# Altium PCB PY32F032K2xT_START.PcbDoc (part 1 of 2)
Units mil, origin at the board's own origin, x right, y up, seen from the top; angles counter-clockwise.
Board outline 1771.65 x 3929.06 mil, 2 copper layers (Top Layer, Bottom Layer), stack 21 mil thick; 141 components, 132 nets, 501 pads, 346 vias.
Unrouted connection lines stored in the file: 5.
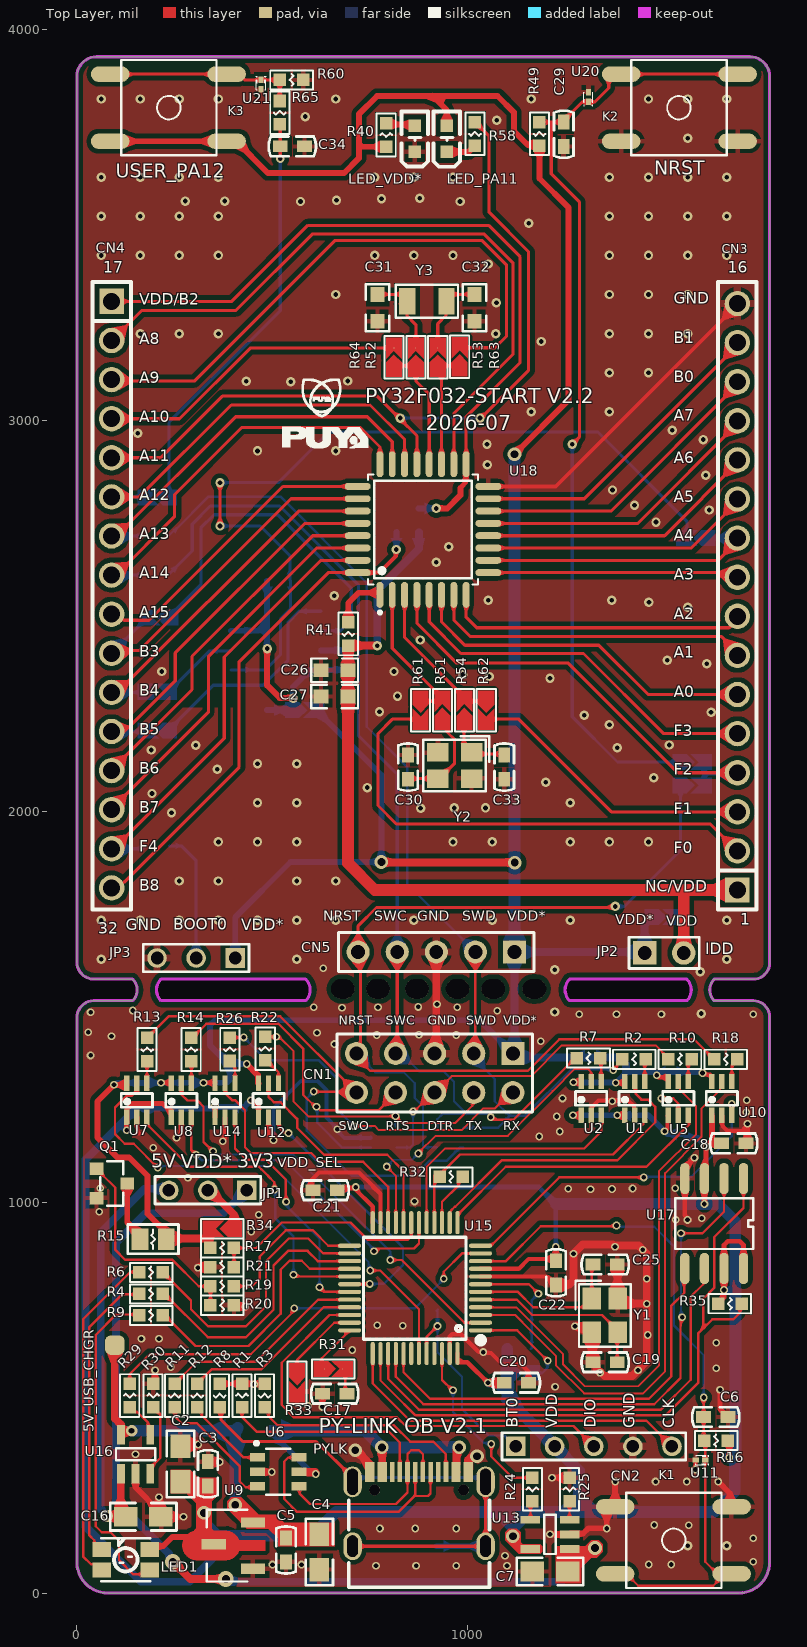
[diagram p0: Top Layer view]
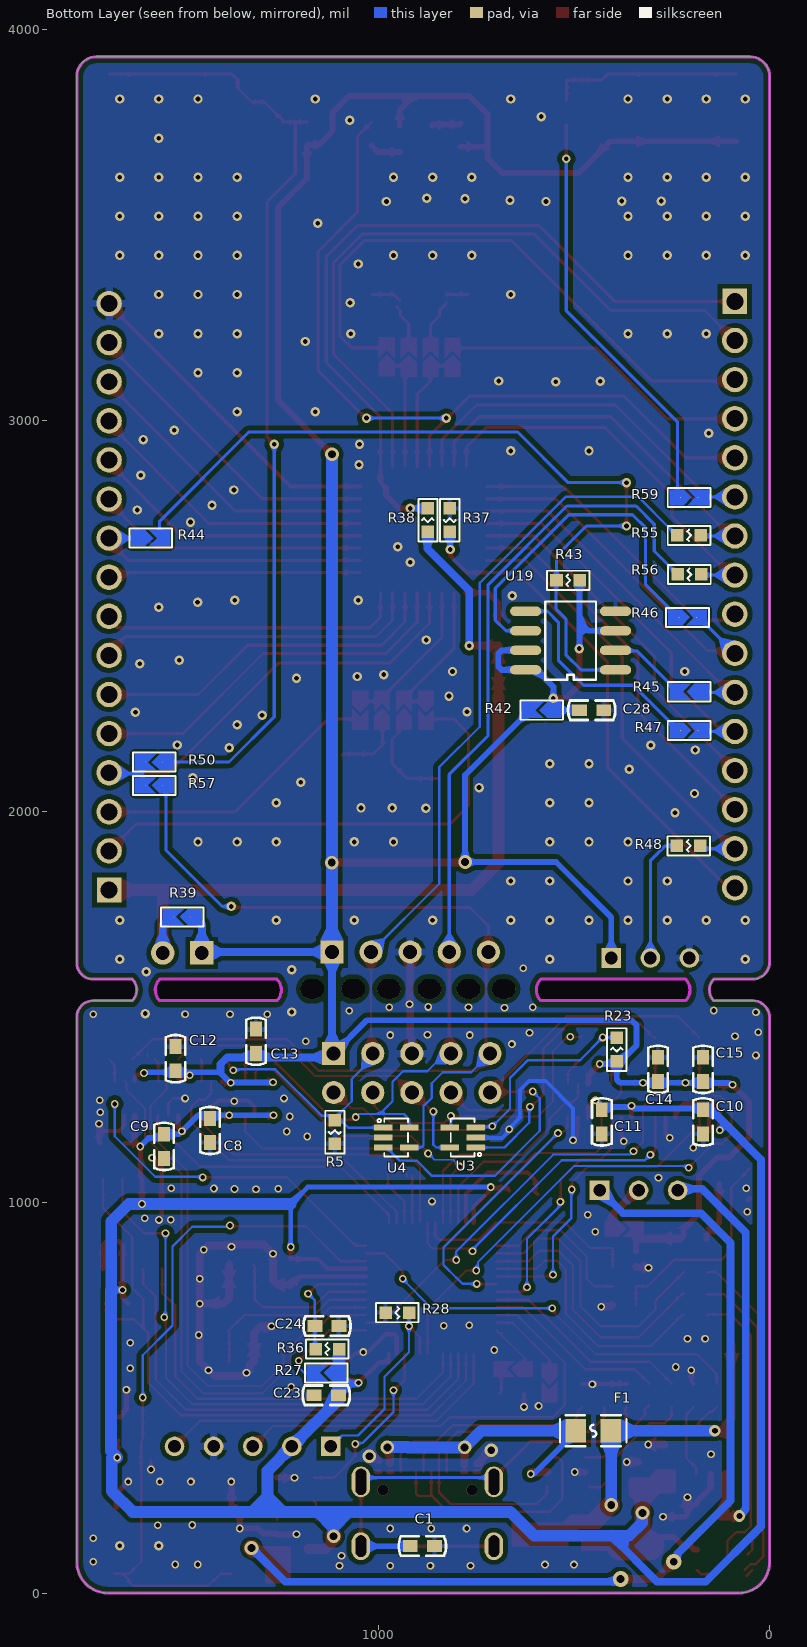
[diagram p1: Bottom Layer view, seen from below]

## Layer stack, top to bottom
Top Solder: solder mask 0.4, Solder Resist, Dk 3.5
Top Layer: signal copper 1.4
Dielectric 2: prepreg 2.8, Composite dielectric, Dk 4.1
Dielectric 1: prepreg 12.6, Composite dielectric, Dk 4.1
Dielectric 3: prepreg 2.8, Composite dielectric, Dk 4.1
Bottom Layer: signal copper 1.4
Bottom Solder: solder mask 0.4, Solder Resist, Dk 3.5

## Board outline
0,78.74 0,1470 cw(c43.75,1471.25) 42.5,1515 142.5,1515 ccw(c115,1542.5) 142.5,1570 42.5,1570 cw(c43.75,1613.75) 0,1615 0,3879.06 cw(c50,3879.06) 50,3929.06 1721.65,3929.06 cw(c1721.65,3879.06) 1771.65,3879.06 1771.65,1611.65 cw(c1730,1611.65) 1730,1570 1630,1570 ccw(c1657.5,1542.5) 1630,1515 1730,1515 cw(c1730,1473.35) 1771.65,1473.35 1771.65,78.74 cw(c1692.91,78.74) 1692.91,0 78.74,0 cw(c78.74,78.74)
cut-out: 1260,1515 cw(c1287.5,1542.5) 1260,1570 1560,1570 cw(c1532.5,1542.5) 1560,1515
cut-out: 215,1515 cw(c242.5,1542.5) 215,1570 585,1570 cw(c557.5,1542.5) 585,1515
cut-out: 215,1515 cw(c242.5,1542.5) 215,1570 585,1570 cw(c557.5,1542.5) 585,1515 565,1515
cut-out: 1260,1515 cw(c1287.5,1542.5) 1260,1570 1560,1570 cw(c1532.5,1542.5) 1560,1515

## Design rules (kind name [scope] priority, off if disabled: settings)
Clearance polygon [InPolygon] p1: gap=12 ignorepadtopadclearanceinfootprint=TRUE
Clearance [All] p2: gap=7 ignorepadtopadclearanceinfootprint=TRUE
HoleToHoleClearance [All] p1: gap=1 allowstackedmicrovias=TRUE
MinimumSolderMaskSliver [All] p1: minsoldermaskwidth=0
PlaneClearance [All] p1: clearance=8
PlaneConnect [All] p1: planeconnectstyle=Direct reliefexpansion=20 reliefentries=4 reliefconductorwidth=10 reliefairgap=10
PolygonConnect [All] p1: thpad.connectstyle=Relief thpad.reliefconductorwidth=20 thpad.reliefentries=4 thpad.polygonreliefangle="90 Angle" thpad.airgapwidth=10 smdpad.connectstyle=Relief smdpad.reliefconductorwidth=12 smdpad.reliefentries=4 smdpad.polygonreliefangle="90 Angle" smdpad.airgapwidth=10 via.connectstyle=Direct via.reliefconductorwidth=10 via.reliefentries=4 via.polygonreliefangle="90 Angle" via.airgapwidth=10
RoutingVias [All] p1: holewidth=28 width=50 viastyle="Through Hole" minholewidth=28 minwidth=50 maxholewidth=28 maxwidth=50
SilkToSilkClearance [All] p1: silktosilkclearance=0
SilkToSolderMaskClearance [IsPad] p1: minsilkscreentomaskgap=0 clearancetoexposedcopper=TRUE
SolderMaskExpansion [All] p1: expansion=4 istentingtop=FALSE
UnRoutedNet [All] p1: checkbadconnections=TRUE
Width [All] p1: maxlimit=100 minlimit=5 preferedwidth=8
23 further rules are at their usual default settings.

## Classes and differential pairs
component class PY32F032K2xT_START: 3 C26 C27 C28 C29 C30 C31 C32 C33 C34 CN3 CN4 CN5 JP2 JP3 K2 K3 LED_PA11 LED_VDD* R37 R38 R39 R40 R41 R42 R43 R44 R45 R46 R47 R48 R49 R50 R51 R52 R53 R54 R55 R56 R57 R58 R59 R60 R61 R62 R63 R64 R65 U18 U19 U20 U21 Y2 Y3
component class PY32F403C1xT_LINK: 5V_USB_CHGR C1 C2 C3 C4 C5 C6 C7 C8 C9 C10 C11 C12 C13 C14 C15 C16 C17 C18 C19 C20 C21 C22 C23 C24 C25 CN1 CN2 F1 JP1 K1 LED1 PYLK Q1 R1 R2 R3 R4 R5 R6 R7 R8 R9 R10 R11 R12 R13 R14 R15 R16 R17 R18 R19 R20 R21 R22 R23 R24 R25 R26 R27 R28 R29 R30 R31 R32 R33 R34 R35 R36 U1 U2 U3 U4 U5 U6 U7 U8 U9 U10 U11 U12 U13 U14 U15 U16 U17 Y1

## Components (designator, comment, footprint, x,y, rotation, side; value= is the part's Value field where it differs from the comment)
5V_USB_CHGR "TP_SIN" TP_SIN 97,634 r90 top
C1 "4.7nF" C0603 888,120 r0 bottom
C2 "10uF" C0805 265,330 r270 top
C3 "100nF" C0603 335,305 r270 top
C4 "10uF" C0805 620,105 r90 top
C5 "100nF" C0603 535,110 r90 top
C6 "100nF" C0603 1634,450 r180 top
C7 "10uF" C0805 1210,55 r0 top
C8 "100nF" C0603 1431,1183 r90 bottom value=104
C9 "100nF" C0603 1548.9,1142.3 r90 bottom value=104
C10 "100nF" C0603 170.2,1204.9 r90 bottom value=104
C11 "100nF" C0603 429,1204.9 r90 bottom value=104
C12 "100nF" C0603 1519.4,1366.6 r270 bottom value=104
C13 "100nF" C0603 1313.8,1411.1 r270 bottom value=104
C14 "100nF" C0603 285.5,1339.2 r270 bottom value=104
C15 "100nF" C0603 170.5,1339.2 r270 bottom value=104
C16 "10uF" C0805 170,195 r180 top
C17 "100nF" C0603 659.59,509.5 r0 top
C18 "100nF" C0603 1680,1150 r180 top value=104
C19 "22pF" C0603 1351.12,590 r0 top
C20 "100nF" C0603 1123.87,537.59 r180 top value=104
C21 "100nF" C0603 635,1030 r0 top value=104
C22 "100nF" C0603 1225.12,819 r90 top value=104
C23 "100nF" C0603 1134,506 r180 bottom value=104
C24 "100nF" C0603 1132,683 r0 bottom value=104
C25 "22pF" C0603 1351.12,840 r180 top
C26 "0.1uF/50V" 0603C 659,2360 r0 top value=2.2uF
C27 "10uF/50V" 0603C 659,2293 r0 top value=2.2uF
C28 "100nF" C0603 455,2258 r0 bottom value=104
C29 "100nF" C0603 1245,3731 r90 top
C30 "22pF" C0603 847.03,2112.4 r270 top
C31 "22pF" 0603C 769,3287 r270 top
C32 "22pF" 0603C 1017,3287 r90 top
C33 "22pF" C0603 1093.03,2112.4 r90 top
C34 "100nF" C0603 551,3700 r180 top
CN1 "2X5P" HDR2X5 1115,1380 r180 top
CN2 "CON5" CON5 1122,375 r0 top
CN3 "X6511WV-18H-C60D30" "CON 1X16P" 1689.29,2648 r90 top
CN4 "X6511WV-18H-C60D30" "CON 1X16P" 89,2453.44 r270 top
CN5 "Header 5" HDR1X5 1119.26,1639.56 r180 top
F1 "JK-SMD0805-050-16V" F0805 451,415 r180 bottom
JP1 "CON3" CON3 435,1030 r180 top
JP2 "CON2" CON2 1452,1637 r0 top
JP3 "CON3" CON3 405,1624.13 r180 top
K1 "TS-KG02S" SWITCH 1527.55,134.7 r180 top
K2 "TS-KG02S" SWITCH 1539,3799 r0 top
K3 "TS-KG02S" SWITCH 236,3798.7 r180 top
LED1 "MHPA3528RGBCT" LED-ARRAY-SMD_4P-L3.5-W2.8-TL 125,85 r0 top
LED_PA11 "GREEN" 0603_LED 947,3733.89 r90 top
LED_VDD* "RED" 0603_LED 865,3734 r90 top
PYLK "KH-TYPE-C-16P" USB-C-SMD_KH-TYPE-C-16P 875.2,214.81 r0 top locked
Q1 "2302" SOT23 89.37,1047.4 r90 top value=SI2302
R1 "5.1K" R0603 422.49,504.99 r270 top
R2 "27R" R0603 1425.21,1365 r180 top
R3 "5.1K" R0603 480,505 r90 top
R4 "680R" R0603 190,765 r0 top
R5 "1M" R0603 1112,1179 r90 bottom
R6 "680R" R0603 190,820 r0 top
R7 "27R" R0603 1308.39,1368.1 r180 top
R8 "1M" R0603 365,505 r90 top
R9 "680R" R0603 190,710 r0 top
R10 "27R" R0603 1542.35,1365 r180 top
R11 "27R" R0603 250,505 r90 top
R12 "27R" R0603 307.5,505 r90 top
R13 "27R" R0603 179.66,1390.08 r90 top
R14 "27R" R0603 292.3,1390.1 r90 top
R15 "100R" R0805 195,905 r0 top
R16 "10K" R0603 1635,390 r0 top
R17 "20K" R0603 371.52,882.61 r180 top
R18 "27R" R0603 1659.49,1365 r180 top
R19 "100R" R0603 371.53,784.78 r0 top
R20 "100K" R0603 371.52,735.88 r180 top
R21 "10K" R0603 371.53,833.69 r0 top
R22 "27R" R0603 481.63,1392.11 r90 top
R23 "4.7K" R0603 391,1390 r270 bottom
R24 "4.7K" R0603 1165,265 r270 top
R25 "16K" R0603 1260,265 r270 top
R26 "27R" R0603 391.2,1390.7 r90 top
R27 "0R" JP2_SMD 1134,563 r180 bottom
R28 "10K" R0603 952,717.08 r0 bottom
R29 "4.7K" R0603 135,505 r270 top
R30 "16K" R0603 195,505 r270 top
R31 "0R" JP2_SMD 656,573 r180 top
R32 "680R" R0603 957.46,1064.37 r0 top
R33 "0R" JP2_SMD 563,538 r90 top
R34 "0R" JP2_SMD 371.52,931.52 r0 top
R35 "100K" R0603 1670,740 r180 top
R36 "10K" R0603 1131,624 r180 bottom
R37 "0R/NC" R0603 818,2744 r90 bottom value=10K
R38 "0R/NC" R0603 874,2744 r270 bottom value=10K
R39 "0R" JP2_SMD 1502,1729 r180 bottom
R40 "680R" R0603 791,3729 r270 top
R41 "0R" R0603 694,2453 r90 top value=10K
R42 "0R/NC" JP2_SMD 583,2258 r180 bottom
R43 "100K" R0603 515,2590 r180 bottom
R44 "0R/NC" JP2_SMD 1583,2698 r0 bottom
R45 "0R/NC" JP2_SMD 206,2305 r180 bottom
R46 "0R/NC" JP2_SMD 210,2495 r0 bottom
R47 "0R/NC" JP2_SMD 206,2206 r0 bottom
R48 "10K" R0603 207,1911 r180 bottom
R49 "10K" R0603 1183,3732 r90 top
R50 "0R" JP2_SMD 1574,2125.25 r180 bottom
R51 "0R" JP2_SMD 935.03,2258.03 r270 top
R52 "0R" JP2_SMD 867,3161 r270 top
R53 "0R" JP2_SMD 923,3161 r270 top
R54 "0R" JP2_SMD 991.03,2258.03 r270 top
R55 "100R" R0603 206,2705 r180 bottom
R56 "100R" R0603 205,2605 r180 bottom
R57 "0R" JP2_SMD 1574,2065.5 r180 bottom
R58 "680Ω" R0603 1018,3732 r90 top value=10K
R59 "0R" JP2_SMD 206,2802 r0 bottom
R60 "1.5K" R0603 549,3870 r180 top
R61 "0R" JP2_SMD 879,2258 r90 top
R62 "0R" JP2_SMD 1047,2258 r90 top
R63 "0R" JP2_SMD 979,3162 r270 top
R64 "0R" JP2_SMD 811,3161 r270 top
R65 "330R" R0603 519,3786 r90 top
U1 "74LVC1T45DW" SOT363 1426.64,1265 r0 top
U2 "74LVC1T45DW" SOT363 1315.21,1265 r0 top
U3 "ESD_6V1" ESD_SOT323-5L 785,1165 r90 bottom value=ESDALC6V1W5
U4 "ESD_6V1" ESD_SOT323-5L 955,1165 r270 bottom value=ESDALC6V1W5
U5 "74LVC1T45DW" SOT363 1538.06,1265 r0 top locked
U6 "USBLC6-2SC6" SOT23-6 515,310 r90 top
U7 "74LVC1T45DW" SOT363 153.55,1260 r0 top locked
U8 "74LVC1T45DW" SOT363 267.26,1260 r0 top
U9 "LM1117-3.3" LM1117-3.3 450.38,62.1 r0 top
U10 "74LVC1T45DW" SOT363 1649.49,1265 r0 top
U11 "ESD-TRANSIL" ESD_ST0201 1595,340 r180 top value=ESDALC6V1-1U2
U12 "74LVC1T45DW" SOT363 490.12,1260 r0 top
U13 "MT9700" SOT23-5 1210,150 r90 top
U14 "74LVC1T45DW" SOT363 378.69,1260 r0 top
U15 "PY32F403C1xT" LQFP-48_L7.0-W7.0-P0.50-LS9.0-BL 865,780 r90 top locked
U16 "MT9700" SOT23-5 150,355 r0 top
U17 "P25Q64SH" SOP-8P 1630,945 r180 top value=SST25VF020B
U18 "PY32F032K2xT" LQFP-32_L7.0-W7.0-P0.80-LS9.0-BL 885.24,2720.01 r0 top
U19 "P25Q64SH" SOP-8P 509,2436 r90 bottom value=SST25VF020B
U20 "ESD-TRANSIL" ESD_ST0201 1308,3825.89 r90 top value=ESDALC6V1-1U2
U21 "ESD-TRANSIL" ESD_ST0201 471,3857.98 r270 top value=ESDALC6V1-1U2
Y1 "24MHz" CRYSTAL-SMD_4P-L3.2-W2.5-BL 1350.12,710 r270 top
Y2 "24MHz" CRYSTAL-SMD_4P-L3.2-W2.5-BL 966.03,2116.4 r180 top
Y3 "32.768KHz" CRYSTAL-SMD_L3.2-W1.5-1 895,3304 r180 top value=X503225MSB2GI

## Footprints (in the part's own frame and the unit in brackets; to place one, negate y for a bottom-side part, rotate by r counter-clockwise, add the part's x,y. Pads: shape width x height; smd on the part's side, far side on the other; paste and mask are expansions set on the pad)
0603_LED [mil]
  rect 31.5x31.5 smd: 1(19,1) 2(-48,1)
  silkscreen extent -86,-33 55,35
0603C [mil]
  rect 38x35 smd: 1(-34.5,0) 2(34.5,0)
  silkscreen extent -60,-30 60,30, body extent -31,-16 32,16, height 12
C0603 [mil]
  rect 38x30 smd: 1(-31,0) 2(31,0)
  silkscreen extent -60,-25 60,25
C0805 [mil]
  rect 60x50 smd: 1(-45,0) 2(45,0)
  silkscreen extent -85,-35 85,35
CON2 [mil]
  rect 60x60 hole 35: 1(0,0)
  round 60 hole 35: 2(100,0)
  silkscreen extent -40,-40 140,40
CON3 [mil]
  rect 50x50 hole 32: 1(0,0)
  round 50 hole 32: 2(100,0) 3(200,0)
  silkscreen extent -35,-35 235,35
CON5 [mil]
  rect 50x50 hole 32: 1(0,0)
  round 50 hole 32: 2(100,0) 3(200,0) 4(300,0) 5(400,0)
  silkscreen extent -35,-35 435,35
"CON 1X16P" [mm]
  rect 1.65x1.6 hole 1.1: 1(-21.59,0)
  round 1.65 hole 1.1: 2(-19.05,0) 3(-16.51,0) 4(-13.97,0) 5(-11.43,0) 6(-8.89,0) 7(-6.35,0) 8(-3.81,0) 9(-1.27,0) 10(1.27,0) 11(3.81,0) 12(6.35,0) 13(8.89,0) 14(11.43,0) 15(13.97,0) 16(16.51,0)
  silkscreen extent -22.86,-1.25 17.92,1.25
CRYSTAL-SMD_4P-L3.2-W2.5-BL [mm]
  rect 1.4x1.2 smd: 1(-1.1,-0.85) 2(1.1,-0.85) 3(1.1,0.85) 4(-1.1,0.85)
  silkscreen extent -2.26,-1.91 2.03,1.68
CRYSTAL-SMD_L3.2-W1.5-1 [mm]
  rect 1.05x1.7 smd: 1(-1.275,0) 2(1.275,0)
  silkscreen extent -2.03,-1.08 2.03,1.08
ESD_SOT323-5L [mm]
  rect 0.4x1.2 smd mask+0.05: 1(-0.65,-0.85) 2(0,-0.85) 3(0.65,-0.85) 4(0.65,0.85) 5(-0.65,0.85)
  silkscreen extent -1.23,-1.21 1.23,0.77, body extent -1.15,-1.05 1.15,1.05, height 1.1
ESD_ST0201 [mm]
  rect 0.425x0.33 smd mask+0.05: 1(-0.312,0) 2(0.312,0)
  silkscreen extent -0.55,-0.3 0.33,0.3, body extent -0.34,-0.18 0.34,0.18, height 0.34
F0805 [mm]
  rect 1.335x1.5 smd paste-100 mask+0.051: 1(-1.142,0) 2(1.142,0)
  silkscreen extent -2.16,-1.02 2.16,1.02
HDR1X5 [mm] "Connector; Header; 5 Position"
  rect 1.5x1.5 hole 0.9: 1(0,0)
  round 1.5 hole 0.9: 2(2.54,0) 3(5.08,0) 4(7.62,0) 5(10.16,0)
  silkscreen extent -1.27,-1.27 11.43,1.27
HDR2X5 [mm] "Connector; Header; 4x2 Position"
  rect 1.5x1.5 hole 0.9: 1(0,0)
  round 1.5 hole 0.9: 2(0,2.54) 3(2.54,0) 4(2.54,2.54) 5(5.08,0) 6(5.08,2.54) 7(7.62,0) 8(7.62,2.54) 9(10.16,0) 10(10.16,2.54)
  silkscreen extent -1.27,-1.27 11.43,3.81
JP2_SMD [mil]
  round 1 smd: 1(21.75,0) 2(-23.03,0.03)
  Top Layer region: -49.77,20.03 -49.77,20.03 3.72,20.03 -16.28,0.03 3.72,-19.98 -49.78,-19.98 -49.78,-19.98
  Top Layer region: -6.25,0 13.75,20 49.75,20 49.75,-20 49.75,-20 13.75,-20
  silkscreen extent -55,-25 54,25
LED-ARRAY-SMD_4P-L3.5-W2.8-TL [mm]
  rect 1.2x0.95 smd: 1(1.55,0.665) 2(1.55,-0.665) 3(-1.55,-0.665) 4(-1.55,0.665)
  silkscreen extent -1.6,-1.4 1.6,1.4
LM1117-3.3 [mm]
  rect 1.575x0.672 smd: 1(0,0) 2(-2.55,1.598) 3(0,3)
  Top Layer region: -3.64,2.459 -1.785,2.459 -1.741,2.458 -1.696,2.455 -1.652,2.449 -1.608,2.442 -1.565,2.433 -1.522,2.421 -1.479,2.408 -1.437,2.393 -1.396,2.375 -1.356,2.356 -1.317,2.335 -1.279,2.312 -1.241,2.288 -1.206,2.261 -1.171,2.233 -1.138,2.204 -1.106,2.173 -1.075,2.14 -1.047,2.106 -1.019,2.071 -0.994,2.034 -0.97,1.996 -0.948,1.958 -0.928,1.918 -0.91,1.839 0.788,1.839 0.788,1.179 -0.91,1.179 -0.928,1.099 -0.948,1.06 -0.97,1.021 -0.994,0.983 -1.019,0.947 -1.047,0.911 -1.075,0.877 -1.106,0.845 -1.138,0.814 -1.171,0.784 -1.206,0.756 -1.241,0.73 -1.279,0.705 -1.317,0.682 -1.356,0.661 -1.396,0.642 -1.437,0.625 -1.479,0.609 -1.522,0.596 -1.565,0.585 -1.608,0.575 -1.652,0.568 -1.696,0.563 -1.741,0.56 -1.785,0.559 -3.64,0.559 -3.684,0.56 -3.728,0.563 -3.773,0.568 -3.817,0.575 -3.86,0.585 -3.903,0.596 -3.946,0.609 -3.988,0.625 -4.029,0.642 -4.069,0.661 -4.108,0.682 -4.146,0.705 -4.183,0.73 -4.219,0.756 -4.254,0.784 -4.287,0.814 -4.319,0.845 -4.349,0.877 -4.378,0.911 -4.405,0.947 -4.431,0.983 -4.455,1.021 -4.477,1.06 -4.497,1.099 -4.515,1.14 -4.531,1.181 -4.546,1.224 -4.558,1.266 -4.568,1.31 -4.577,1.353 -4.583,1.398 -4.587,1.442 -4.589,1.486 -4.589,1.531 -4.587,1.575 -4.583,1.62 -4.577,1.664 -4.568,1.708 -4.558,1.751 -4.546,1.794 -4.531,1.836 -4.515,1.877 -4.497,1.918 -4.477,1.958 -4.455,1.996 -4.431,2.034 -4.405,2.071 -4.378,2.106 -4.349,2.14 -4.319,2.173 -4.287,2.204 -4.254,2.233 -4.219,2.261 -4.183,2.288 -4.146,2.312 -4.108,2.335 -4.069,2.356 -4.029,2.375 -3.988,2.393 -3.946,2.408 -3.903,2.421 -3.86,2.433 -3.817,2.442 -3.773,2.449 -3.728,2.455 -3.684,2.458
  silkscreen extent -3.01,-0.83 -0.35,3.83
LQFP-32_L7.0-W7.0-P0.80-LS9.0-BL [mm]
  oval 0.448x1.684 smd: 1(-2.8,-4.242) 2(-2,-4.242) 3(-1.2,-4.242) 4(-0.4,-4.242) 5(0.4,-4.242) 6(1.2,-4.242) 7(2,-4.242) 8(2.8,-4.242) 17(2.8,4.242) 18(2,4.242) 19(1.2,4.242) 20(0.4,4.242) 21(-0.4,4.242) 22(-1.2,4.242) 23(-2,4.242) 24(-2.8,4.242)
  oval 1.684x0.448 smd: 9(4.242,-2.8) 10(4.242,-2) 11(4.242,-1.2) 12(4.242,-0.4) 13(4.242,0.4) 14(4.242,1.2) 15(4.242,2) 16(4.242,2.8) 25(-4.242,2.8) 26(-4.242,2) 27(-4.242,1.2) 28(-4.242,0.4) 29(-4.242,-0.4) 30(-4.242,-1.2) 31(-4.242,-2) 32(-4.242,-2.8)
  silkscreen extent -3.58,-5.48 3.58,3.58
LQFP-48_L7.0-W7.0-P0.50-LS9.0-BL [mm]
  oval 0.27x1.5 smd mask+0.05: 1(-2.75,-4.25) 2(-2.25,-4.25) 3(-1.75,-4.25) 4(-1.25,-4.25) 5(-0.75,-4.25) 6(-0.25,-4.25) 7(0.25,-4.25) 8(0.75,-4.25) 9(1.25,-4.25) 10(1.75,-4.25) 11(2.25,-4.25) 12(2.75,-4.25) 25(2.75,4.25) 26(2.25,4.25) 27(1.75,4.25) 28(1.25,4.25) 29(0.75,4.25) 30(0.25,4.25) 31(-0.25,4.25) 32(-0.75,4.25) 33(-1.25,4.25) 34(-1.75,4.25) 35(-2.25,4.25) 36(-2.75,4.25)
  oval 1.5x0.27 smd mask+0.05: 13(4.25,-2.75) 14(4.25,-2.25) 15(4.25,-1.75) 16(4.25,-1.25) 17(4.25,-0.75) 18(4.25,-0.25) 19(4.25,0.25) 20(4.25,0.75) 21(4.25,1.25) 22(4.25,1.75) 23(4.25,2.25) 24(4.25,2.75) 37(-4.25,2.75) 38(-4.25,2.25) 39(-4.25,1.75) 40(-4.25,1.25) 41(-4.25,0.75) 42(-4.25,0.25) 43(-4.25,-0.25) 44(-4.25,-0.75) 45(-4.25,-1.25) 46(-4.25,-1.75) 47(-4.25,-2.25) 48(-4.25,-2.75)
  silkscreen extent -3.59,-4.46 3.3,3.34
R0603 [mil]
  rect 32x32 smd: 1(-30,0) 2(30,0)
  silkscreen extent -55,-24 54,25
R0805 [mm]
  rect 1.1x1.4 smd: 1(-0.85,0) 2(0.85,0)
  silkscreen extent -1.65,-0.95 1.65,0.95
SOP-8P [mil]
  oval 24x80 smd: 1(-75,-115) 2(-25,-115) 3(25,-115) 4(75,-115) 5(75,115) 6(25,115) 7(-25,115) 8(-75,115)
  silkscreen extent -100,-65 100,65
SOT23 [mm]
  rect 0.8x0.9 smd: 1(0.95,1) 2(-0.95,1) 3(0,-1)
  silkscreen extent -1.45,-0.75 1.45,0.75
SOT23-5 [mil]
  rect 20x50 smd: 1(-37.5,-50) 2(0,-50) 3(37.5,-50) 4(37.5,50) 5(-37.5,50)
  silkscreen extent -50,-15 50,15
SOT23-6 [mm]
  rect 0.55x1 smd: 1(0.95,1.35) 2(0,1.35) 3(-0.95,1.35) 4(-0.95,-1.35) 5(0,-1.35) 6(0.95,-1.35)
  silkscreen extent -1.5,-0.8 1.96,1.52
SOT363 [mm]
  rect 0.35x1 smd: 1(-0.65,-1.1) 2(0,-1.1) 3(0.65,-1.1) 4(0.65,1.1) 5(0,1.1) 6(-0.65,1.1)
  silkscreen extent -1.02,-0.45 1.02,0.45, body extent -1,-1.1 1,1.16, height 1
SWITCH [mm]
  oval 2.5x1 smd: 1(-3.734,2.177) 2(3.835,2.177) 3(-3.734,-2.184) 4(3.835,-2.184)
  silkscreen extent -3.08,-3.1 3.12,3.09, body extent -4.48,-3 4.52,3, height 8.95
TP_SIN [mil]
  rrect60% 50x50 smd: 1(0,0)
USB-C-SMD_KH-TYPE-C-16P [mm]
  oval 1.2x2 hole 0.7 slot 1.7 at 90 deg: 1(-4.32,1.765) 2(4.32,1.765)
  oval 1.2x1.8 hole 0.7 slot 1.4 at 90 deg: 3(-4.32,-2.415) 4(4.32,-2.415)
  rect 0.3x1.3 smd: A1(-3.35,2.415) A4(-2.55,2.415) A5(-1.25,2.415) A6(-0.25,2.415) A7(0.25,2.415) A8(1.25,2.415) A9(2.55,2.415) A12(3.35,2.415) B1(3.05,2.415) B4(2.25,2.415) B5(1.75,2.415) B6(0.75,2.415) B7(-0.75,2.415) B8(-1.75,2.415) B9(-2.25,2.415) B12(-3.05,2.415)
  round 0.7 hole 0.7 unplated: ""(-2.89,1.235) ""(2.89,1.235)
  silkscreen extent -4.57,-5.08 4.57,0.57

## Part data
C1 C3 C5 C6 C17 C19 C25 C29 C30 C33 C34: library part C0603
C2 C4 C7 C16: library part C0805
C8 C9 C10 C11 C12 C13 C14 C15 C18 C20 C21 C22 C23 C24 C28: library part 贴片高压陶瓷电容, "Capacitor (Semiconductor SIM Model)"
C26 C27: library part CAP, "Capacitor"
C31 C32: library part Cap, "Capacitor"
CN1: Color=黑色, Current Rating (Max)=-, JLCPCB Part Class="Extended Part", LCSC Part Name="间距:2.54mm 2x5P 直插 方针", Manufacturer=XFCN(兴飞), Manufacturer Part=PZ254V-12-10P, Operating Temperature Range=-40℃~+105℃
CN3 CN4: library part "CON 1X16P", Color=黑色, Current Rating (Max)=3A, JLCPCB Part Class="Extended Part", LCSC Part Name="1x18P 间距:2.54mm 方针", Manufacturer="XKB Connection(中国星坤)", Operating Temperature Range=-40℃~+105℃, Soldering Temperature(Max)=260℃, Voltage Rating (Max)=250V
CN5: "Header, 5-Pin"
F1: Current - Max=100A, Hold Current=500mA, JLCPCB Part Class="Extended Part", LCSC Part Name="6V 0.5A 贴片自恢复", Manufacturer=JK(金科), Operating Temperature=-40℃~+85℃, Power Dissipation=600mW, Resistance - Initial (Ri) (Min)=150mΩ, Resistance - Post Trip (R1) (Max)=850mΩ, Trip Current=1A, Voltage - Max=6V
JP2: library part CON2_DIP
K1 K2 K3: library part TS-KG02S-AT50F, Actuator/Cap Color=黑色, Contact Current=50mA, Insulation Resistance=100MΩ, JLCPCB Part Class="Extended Part", LCSC Part Name="6*6*5mm 立贴 轻触开关", Manufacturer=HANBO(汉博), Operating Force=250gf, Voltage Rating (DC)=12V
LED1: JLCPCB Part Class=扩展库, LCSC Part Name=RGB三色, Manufacturer=MEIHUA(美华)
LED_PA11 LED_VDD*: library part PDI-E803_Dup1
PYLK: BOM_JLCPCB Part Class="Extended Part", BOM_Manufacturer="Shenzhen Kinghelm Elec"
Q1: library part "MOSFET N", "MOSFET N"
R1 R2 R3 R4 R5 R6 R7 R8 R9 R10 R11 R12 R13 R14 R16 R17 R18 R19 R20 R21 R22 R23 R24 R25 R26 R27 R28 R29 R30 R31 R32 R33 R34 R35 R36 R39 R40 R42 R43 R44 R45 R46 R47 R48 R49 R50 R51 R52 R53 R54 R55 R56 R57 R59 R60 R61 R62 R63 R64 R65: library part R0603
R15: library part R0805
R37 R38 R41 R58: library part Res, "Resistor"
U3 U4: library part ESDALC6V1W5, "Dual Transil array for ESD protection", Manufacturer=STMICROELECTRONICS
U11 U20 U21: "ESD protection 6V1", Manufacturer=STMICROELECTRONICS, Manufacturer_Part_Number=ESDALC6V1-1U2
U15: "LQFP48", BOM_Manufacturer=PUYA(普冉)
U17 U19: library part SST25VF010, "SST25VF010"
U18: "LQFP32(7*7)", BOM_Manufacturer=PUYA(普冉)
Y1 Y2: library part ABM8AIG-24.000MHZ-82Z-T, "±20ppm , 12.5pF , T_use: -40°C~125°C", Equivalent Series Resistance (ESR)=50Ω, External load capacitor=8pF, Frequency Stability(Full temperature range)=±50ppm, JLCPCB Part Class="Extended Part", LCSC Part Name="24MHz ±20ppm 8pF", Manufacturer=ABRACON, Normal temperature Frequency Tolerance=±20ppm, Operating Temperature=-40℃~+125℃
Y3: library part CRYSTAL_1, "Crystal"

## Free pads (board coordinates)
  oval 60x50 hole 50 slot 60 at 0 deg unplated: 1(680,1545) 1(770,1545) 1(870,1545) 1(973.55,1545) 1(1065,1545) 1(1170,1545)

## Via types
v1: diameter 24, hole 12, Top Layer to Bottom Layer, tented both sides, 164 vias
v2: diameter 19.68, hole 11.81, Top Layer to Bottom Layer, tented both sides, 128 vias
v3: diameter 19.68, hole 11.81, Top Layer to Bottom Layer, 38 vias
v4: diameter 35, hole 20, Top Layer to Bottom Layer, tented both sides, 11 vias
v5: diameter 30, hole 15, Top Layer to Bottom Layer, tented both sides, 2 vias
v6: diameter 40, hole 20, Top Layer to Bottom Layer, tented both sides, 2 vias
v7: diameter 22, hole 12, Top Layer to Bottom Layer, 1 vias

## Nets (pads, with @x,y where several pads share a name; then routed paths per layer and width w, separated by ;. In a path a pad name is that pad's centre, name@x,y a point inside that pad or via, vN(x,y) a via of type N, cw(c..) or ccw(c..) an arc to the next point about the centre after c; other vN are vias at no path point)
3.3V_OUT_EN: R24.1 U15.46 | length 453.7
  Top Layer w6: U15.46@933.9,612.68 933.9,545.1 960,519 v2(962,519) ; v2(1060,381.16) 1060,349.4 1114.4,295 R24.1@1165,295
  Bottom Layer w6: v2(962,519) 962,463 1041.22,383.78 1057.38,383.78 v2(1060,381.16)
3V3_PYLK: C2.2 C3.2 C8.2 C9.2 C10.2 C11.2 C18.2 C20.2 C21.2 C22.2 C23.2 CN2.2 LED1.1 R16.2 R27.1 R35.2 R36.2 U1.1 U2.1 U5.1 U7.1 U8.1 U9.2 U10.1 U12.1 U13.5 U14.1 U15.9 U15.24 U15.48 U17.3 U17.7 U17.8 | length 7855.5
  Top Layer w10: v2(445.16,1260.63) 449.42,1260.63 464.53,1245.52 U12.1@464.53,1216.69 ; C21.2@666,1030 C21.2@670.66,1034.66 ; C22.2@1225,854.12 v2(1225,885) ; R16.2@1665,390 1668.22,386.78 v2(1668.22,346.75)
  Top Layer w11: v2@710,1035 756.73,988.27 U15.24@756.73,947.32 ; U15.48@973.27,612.68 973.27,590.61 973.45,590.42 998.23,590.42 1053.65,535 v2@1055.12,535 ; U15.9@1032.32,829.21 1130.39,829.21 1155.3,854.12 C22.2@1225,854.12
  Top Layer w12: v3(127.35,1183.66) 127.96,1184.27 U7.1@127.96,1216.69 127.96,1237.87 141.96,1251.88 219.81,1251.88 241.67,1230.01 U8.1@241.67,1216.69 ; U14.1@353.1,1216.69 353.99,1217.58 353.12,1218.46 v2(353.12,1246.39) ; C21.2@670.66,1034.66 671.99,1035.99 710.99,1035.99 v2(713.28,1038.28) ; v2(1268.73,1222.03) 1269.06,1221.69 U2.1@1289.62,1221.69 ; v2(1382,1221.9) 1382.21,1221.69 U1.1@1401.05,1221.69 ; v3(1503.01,1181.02) 1512.47,1190.48 U5.1@1512.47,1221.69 1511.58,1220.8 U5.1@1511.8,1220.58 ; v2(1605,995) U17.3@1605,1060 1609.01,1064.01 1609.01,1141.25 v2(1609.87,1142.11) ; 1617.76,1150 C18.2@1649,1150 ; R35.2@1640,740 1655,755 v2(1655,775) U17.7@1655,830 1655,890 1665,900 1695,900 1705,890 U17.8@1705,830
  Top Layer w15: LED1.1@186.02,111.18 193.48,111.18 193.48,111.66 202.14,120.32 221.03,120.32 244.3,143.59 313.8,143.59 ; v2(1609.87,1142.11) 1617.76,1150 1623.9,1156.14 U10.1@1623.9,1221.69
  Top Layer w20: v2@1054.87,537.59 C20.2@1092.87,537.59
  Bottom Layer w12: v2(713.28,1038.28) 1181.72,1038.28 1225,995 ; v2(1225,885) 1225,990 ; v2(1655,775) 1683.73,775 1684.65,775
  Bottom Layer w15: C10.2@170.2,1235.9 173.64,1239.34 346.07,1239.34 v2(353.12,1246.39) 356.92,1242.6 422.3,1242.6 C11.2@429,1235.9 429,1244.47 v2(445.16,1260.63) v2@443.56,1262.22 ; v2(1268.73,1222.03) 1431,1222.03 1462,1222.03 v3(1503.01,1181.02) 1510.73,1173.3 C9.2@1548.9,1173.3 ; C9.2@1558.32,1163.88 1588.1,1163.88 v2(1609.87,1142.11)
  Bottom Layer w20: v3(127.35,1183.66) 112.87,1198.15 111.65,1198.15 ; C10.2@170.2,1244.2 157.7,1244.2 111.65,1198.15 ; 405.3,146.25 287.88,28.84 163.16,28.84 22,170 22,1108.5 111.65,1198.15 ; v2(1051.39,538) 1053.39,536 1103,536
  Bottom Layer w30: v4(325,205) 325.96,204.04 325.96,179.91 359.61,146.25 405.3,146.25 602.14,146.25 663.2,207.32 1115.96,207.32 ; C23.2@1099.5,497.5 CN2.2@1222,375 1284,313 1284,207.32 ; R36.2@1101,624 1101,574.25 R27.1@1112.25,563 1103,553.75 1103,536 C23.2@1103,506 ; v4(1115,145) 1115.96,145.96 1115.96,207.32 ; 1225,995 v2(1605,995) 1638.96,995 1683.73,950.23 1683.73,775 ; v2(1668.22,346.75) 1684.65,363.18 1684.65,775 ; 1682.7,345 1682.7,260.85 1629.17,207.32 1284,207.32 ; 1115.96,207.32 1284,207.32
3V3_USB_PYLK: C7.2 JP1.1 U13.1 | length 2404.2
  Top Layer w20: v6@245.8,80 290.03,35.77 v6(380.96,35.77)
  Bottom Layer w20: v6(245,80) 245,85.41 235.27,95.14 235.27,100.98 100.1,236.16 100.1,895.86 175.6,971.36 374.6,971.36 418.24,1015 420,1015 433.24,1028.24 JP1.1@433.24,1030 ; v6(380.96,35.77) 387.82,28.91 1238.91,28.91 v4(1325,115) v4@1326.78,113.22
5V_OUT_EN: R29.1 U15.11 | length 1065.3
  Top Layer w6: R29.1@135,535 135,560 185.65,610.65 444.42,610.65 555.92,722.16 v2(555.92,728.42) ; v2(938.27,804.07) 938.27,821.87 984.98,868.58 U15.11@1032.32,868.58
  Bottom Layer w6: v2(555.92,728.42) 864.41,728.42 938.27,802.29 v2(938.27,804.07)
5V_USB_CHGR: 5V_USB_CHGR.1 C4.2 C5.2 F1.2 U9.3 U16.5 | length 733.9
  Top Layer w20: 5V_USB_CHGR.1@97,634 97,446.71 112.5,431.21 U16.5@112.5,405 ; U16.5@112.5,413.09 138.09,413.09 v5(140,415)
  Bottom Layer w30: v5(140,415) 407.02,415 F1.2@410.02,418 ; v4@405,226.35 405,416.22 F1.2@411.4,422.62
  other v4: 405,225
5V_USB_PYLK: C16.2 JP1.3 U16.1 | length 1109.9
  Top Layer w20: v5(77.39,196.82) 78.3,195.91 124.09,195.91 C16.2@125,195 ; U16.1@112.5,304.69 112.5,290 112.19,289.69 112.19,210 C16.2@125,210
  Bottom Layer w20: v5(77.39,196.82) 74.92,197.32 71.21,201.03 69.81,202.43 60.92,215.77 60.92,921.89 172.85,1033.82 231.18,1033.82 JP1.3@235,1030
AD_TVDD: R17.1 R21.2 U15.19 | length 586.3
  Top Layer w6: R21.2@401.52,833.7 R17.1@401.52,882.61 458.79,882.61 523.97,947.79 699.66,947.79 743.59,903.86 846.86,903.86 855.16,912.17 U15.19@855.16,947.32
BOOT0: CN4.15 R48.2 U18.31 | length 1153.5
  Top Layer w8: CN4.15@89,1903.44 94.46,1903.44 377,2185.98 377,2394 624.16,2641.16 U18.31@723.99,2641.16
  Bottom Layer w8: CN4.15@89,1903.44 169.44,1903.44 R48.2@177,1911
DIR_RESET: U10.5 U15.3 | length 1394.2
  Top Layer w5: U15.3@1032.32,711.1 1120.66,711.1 1160.03,671.73 1225.22,606.55 1225.22,582.77 1297.49,510.5 1448.41,510.5 1504.53,566.63 1504.53,1074.04 1596.97,1166.47 1596.97,1238.45 1645.1,1286.59 1645.1,1303.92 U10.5@1649.49,1308.31
DIR_RTCK_DTR: U5.5 U15.4 | length 1362.6
  Top Layer w5: U15.4@1032.32,730.79 1123.69,730.79 1163.06,691.42 1243.43,611.05 1243.43,584.49 1299.09,528.83 1435.95,528.83 1488.53,581.41 1488.53,1078.32 1583.97,1173.76 1583.97,1245.09 1542.45,1286.6 1542.45,1303.92 U5.5@1538.06,1308.31
DIR_TCK_SWCLK: U2.5 U15.21 | length 808
  Top Layer w5: v2(792.12,1090.67) 815.79,1067 U15.21@815.79,947.32 ; v3(873.49,1124.13) 873.49,1125.57 917.33,1169.41 1102.34,1169.41 1216.71,1283.79 1273.38,1340.46 1307.19,1340.46 1315.21,1332.43 U2.5@1315.21,1308.31
  Bottom Layer w5: v2(792.12,1090.67) 809.61,1108.16 857.52,1108.16 v3(873.49,1124.13)
DIR_TDI_VCP_TX: U12.5 U15.20 | length 603.7
  Top Layer w6: U12.5@490.12,1303.31 490.12,1268.77 503.92,1254.98 520.97,1254.98 563.25,1212.7 563.25,1189.92 632.11,1121.06 793.64,1121.06 835.47,1079.24 U15.20@835.47,947.32
DIR_TDO_SWO: U7.5 U15.43 | length 1250.3
  Top Layer w6: U7.5@153.55,1303.31 153.55,1284.73 140.19,1271.38 127.22,1271.38 97.4,1241.56 97.4,1174.28 122.48,1149.2 145.25,1149.2 v3(206.55,1087.9) ; v2(750,825) 775.69,825 874.84,725.85 U15.43@874.84,612.68
  Bottom Layer w5: v3(206.55,1087.9) 211.05,1092.41 500.21,1092.41 746.36,846.25 746.36,828.64 v2(750,825)
DIR_TMS_SWDIO: U1.5 U15.14 | length 784.3
  Top Layer w6: U15.14@953.58,947.32 953.58,973.99 956.95,977.36 956.95,978.29 966.51,987.85 967.44,987.85 1086.13,1106.54 1381.8,1106.54 1479.4,1204.13 1479.4,1243.36 1460.78,1261.98 1443.79,1261.98 1428.52,1277.25 1428.52,1306.42 U1.5@1426.64,1308.31
DIR_TRST_RTS: U8.5 U15.2 | length 1100.7
  Top Layer w6: U8.5@267.26,1303.31 267.85,1302.72 267.85,1274.24 282.53,1259.56 308.14,1259.56 323.94,1243.76 323.94,1153.79 v2(348.06,1129.67) ; v2(801.52,851.68) 830.72,851.68 990.98,691.42 U15.2@1032.32,691.42
  Bottom Layer w5: v2(348.06,1129.67) 356.33,1121.41 553.59,1121.41 801.52,873.48 v2(801.52,851.68)
DIR_VCP_RX: U14.5 U15.22 | length 688.5
  Top Layer w6: U14.5@378.69,1303.31 380.07,1301.93 380.07,1277.14 396.6,1260.6 404.2,1260.6 430,1234.81 430,1140.06 444.61,1125.45 599.3,1125.45 622.05,1102.71 732.18,1102.71 776.38,1058.51 796.1,1038.79 U15.22@796.1,947.32
F_VDD: C28.2 R42.1 R43.2 U19.3 U19.7 U19.8 | length 845.3
  Top Layer w15: v1(486.52,2415.48) 486.52,2321.48 518.5,2289.5 551.5,2289.5 v1(553,2288)
  Bottom Layer w15: U19.3@394,2461 464.13,2461 486.03,2482.9 ; C28.2@486,2258 553,2258 v1(553,2288) 553,2318 596,2361 U19.8@624,2361 685.21,2361 694,2369.79 694,2402.21 685.21,2411 U19.7@624,2411 ; R43.2@486.03,2588.97 486.03,2482.9 ; v1@487,2415 v1(486.52,2415.48) 486.03,2415.97 486.03,2482.9
GND: C1.1 C2.1 C3.1 C4.1 C5.1 C6.1 C7.1 C8.1 C9.1 C10.1 C11.1 C12.1 C13.1 C14.1 C15.1 C16.1 C17.1 C18.1 C19.1 C20.1 C21.1 C22.1 C23.1 C24.1 C25.1 C26.1 C27.1 C28.1 C29.1 C30.1 C31.2 C32.1 C33.1 C34.1 CN1.5 CN2.4 CN3.16 CN5.3 JP3.3 K1.3 K1.4 K2.3 K2.4 LED_VDD*.2 PYLK.A1 PYLK.A12 PYLK.B1 PYLK.B12 Q1.2 R1.1 R3.2 R5.1 R8.2 R20.1 R21.1 R25.1 R28.2 R30.1 R33.2 R37.2 R60.1 U1.2 U2.2 U3.2 U4.2 U5.2 U6.2 U7.2 U8.2 U9.1 U10.2 U11.2 U12.2 U13.2 U14.2 U15.8 U15.23 U15.47 U16.2 U17.4 U18.16 U19.4 U20.2 U21.2 Y1.2 Y1.4 Y2.2 Y2.4 | length 5516.4
  Top Layer w6: v2(1495,1265) 1525,1265 1538.06,1251.94 U5.2@1538.06,1221.69 ; v2(1582,316) 1582.35,316.35 1582.35,339.65 U11.2@1582.7,340
  Top Layer w10: U7.2@153.55,1216.69 154.54,1215.7 154.54,1180.08 159.36,1175.25 ; R30.1@195,535 200,540 v2(200,570) ; C16.1@210,210 210,200 C16.1@215,195 ; v2(255,1164.6) 265.89,1175.49 265.89,1215.32 U8.2@267.26,1216.69 ; C2.1@265,375 C2.1@270,380 ; C3.1@335,336 C3.1@336,335 ; R8.2@365,535 v2@453.95,535 ; v2(372.9,1155.7) 378.59,1161.39 U14.2@378.59,1216.59 ; R20.1@401.52,735.88 R20.1@403.04,737.4 ; v2(453.1,534.15) v2@453.95,535 ; R3.2@480,535 v2@453.95,535 ; U12.2@490.12,1216.69 491.41,1215.4 491.41,1172.62 501.83,1162.2 501.83,1156.83 v2@500,1155 ; C21.1@593.36,1020 603.36,1030 C21.1@604,1030 597.95,1036.05 597.95,1054.14 619.23,1075.42 721.98,1075.42 756.82,1040.58 ; v3(628,476) 628,508.9 C17.1@628.59,509.5 ; PYLK.A1@743.31,309.89 PYLK.B12@755.12,309.89 ; PYLK.B1@995.28,309.89 PYLK.A12@1007.09,309.89 ; v2@1039.47,613.56 v2@1039.6,613.69 ; v2@1041.61,614.02 1059.36,614.02 1088.57,584.8 1137.07,584.8 1154.91,566.95 C20.1@1154.87,537.59 ; U18.16@1046.79,2830.06 1224.82,2830.06 1692.76,3298 CN3.16@1697,3298 ; U2.2@1314.26,1220.75 1317.1,1223.58 1317.1,1242.95 1334.15,1260 v2@1370.02,1260 ; v2(1369.2,1257.6) 1370.02,1258.42 v2@1370.02,1260 ; U1.2@1426.64,1221.69 1424.75,1223.58 1424.75,1245.25 1410,1260 v2@1370.02,1260 ; U10.2@1649.49,1221.69 1651.38,1219.8 1651.38,1193.96 1663.61,1181.72 1715,1181.72
  Top Layer w11: 756.82,1040.58 776.42,1020.98 U15.23@776.42,947.32 ; U15.47@953.58,612.68 953.58,655.91 959.74,662.07 982.08,662.07 1027.87,616.28 v2(1039.35,616.28) ; U15.8@1032.32,809.53 1199.94,809.53 1221.47,788 C22.1@1225.12,788
  Top Layer w12: Q1.2@50.2,1009.8 Q1.2@55.01,1004.99 ; v2(1561.71,954.27) 1566.84,954.27 1555,966.11 1555,1088.88 1579.39,1113.27 v2(1579.39,1113.51) ; v2(1645,520) 1645,470 1652,463 1652,459 1661,450 C6.1@1665,450 ; C18.1@1711,1150 1715,1154 1715,1181.72 v2(1715,1200)
  Top Layer w15: U16.2@149.48,304.48 150.91,303.04 150.91,269.09 C16.1@210,210 ; C16.1@215,195 v2(272.56,195) ; U6.2@470.66,310.05 472.24,308.47 473.29,309.52 v2(498.08,309.52) ; v2(1210,150) U13.2@1260,150 1262.16,152.16 1294.66,152.16 1308.23,165.74 v2@1354.26,165.74 ; v2(1215,295) R25.1@1260,295 ; v2(1355,165) 1355,209.44 1366.26,220.7 K1.4@1376.55,220.7 v2(1376.55,285) ; v2(1640,285) 1670.55,254.45 K1.3@1670.55,221
  Top Layer w20: C16.1@210,210 v2(210,245) ; C2.1@270,380 v2(310,380) ; v2(309.83,832.29) 310.59,833.04 341.17,833.04 R21.1@341.93,833.8 ; C3.1@336,335 v2(365,335) ; R20.1@403.04,737.4 403.04,737.12 407.52,732.64 429.94,732.64 v2(430.7,731.87) ; v4(712.08,365) 715.03,365 PYLK.A1@749.17,330.85 ; CN1.5@915,1380 919.26,1384.26 CN5.3@919.26,1639.56 ; 999.5,339.28 1007.35,347.13 1020.68,347.13 v4(1023.55,350) ; C22.1@1220.12,797 1225.12,792 C22.1@1225.12,788 1225.41,788.28 1258.41,788.28 1270.12,800 v2(1270.12,867.57) 1293.95,891.41 1370.41,891.41 v2(1376.26,885.55) 1377.35,885.55 1380.45,888.65 1436.47,888.65 v2(1447.03,878.1) 1457.58,867.54 v2(1457.58,803.85) 1457.58,740.13 1457.58,592.46 v2(1435.12,570) 1419.85,554.73 1349.89,554.73 v2@1339.64,564.98 ; v2(1273.98,682.29) 1301.06,682.29 Y1.2@1316.66,666.69 1318.39,664.96 1318.39,591.73 C19.1@1320.12,590 1324.12,590 1329.12,585 1329.12,575.5 1330.37,574.25 ; 1330.37,570.63 v2(1337.83,563.18) ; C25.1@1382.12,840 1382.85,839.27 1382.85,754.04 Y1.4@1383.59,753.31 1396.74,740.16 v2(1457.55,740.16)
  Bottom Layer w6: v2@499.26,1157.83 v2(502.89,1157.83)
  Bottom Layer w10: v2(502.89,1157.83) 502.89,1239.49 572.46,1309.06 615.72,1309.06 638,1286.78 638,1215.79 665.89,1187.9 v2(665.89,1185.89) ; v2@665,1183 683.72,1164.28 750.81,1164.28 U3.2@751.54,1165
  Bottom Layer w20: CN1.5@915,1380 CN1.5@921,1386
  other v1: 1562,121 1662,121 1597,1482 1222,1486 1594,1589 1222,1594 62,1621 562,1621 1662,1621 62,1721 162,1721 262,1721 362,1721 462,1721 562,1721 662,1721 862,1721 1062,1721 1262,1721 1662,1721 262,1821 362,1821 562,1821 662,1821 362,1921 462,1921 562,1921 962,1921 1062,1921 1262,1921 1362,1921 1462,1921 242,1996 879,2007 965,2008 1045,2008 462,2021 562,2021 1262,2021 192,2045 743,2060 1199,2074 1475,2085 359,2107 462,2121 562,2121 190,2156 1382,2162 304,2168 1515,2169 1362,2221 1298,2245 1622,2253 774,2254 820,2294 1210,2340 1055,2344 987,2349 217,2357 811,2357 1611,2377 1510,2386 878.47,2437.47 1562,2521 1463,2534 1052,2539 1368,2539 658,2551 919,2636 951,2676 1481,2739 1617,2770 1426,2782 1370,2821 1608,2859 1050,2886 462,2921 662,2921 1049,2938 1602,2950 156,2966 1523,2974 1162,3021 1362,3021 547,3098 433,3099 693,3100 1362,3121 1462,3121 1188,3201 162,3221 262,3221 362,3221 1071,3221 1362,3221 1462,3221 1562,3221 1073,3300 662,3321 1362,3321 1462,3321 1562,3321 1052,3399 62,3421 162,3421 262,3421 362,3421 762,3421 862,3421 962,3421 1362,3421 1462,3421 1562,3421 1662,3421 1156,3503 62,3521 162,3521 262,3521 362,3521 1362,3521 1462,3521 1562,3521 1662,3521 572,3559 980,3559 277,3560 378,3560 664,3562 779,3566 877,3567 62,3621 162,3621 262,3621 362,3621 762,3621 862,3621 962,3621 1362,3621 1462,3621 1562,3621 1662,3621 1562,3721 1074,3767 583.95,3776.18 62,3821 162,3821 262,3821 362,3821 662,3821 1162,3821 1462,3821 1562,3821 1662,3821
  other v2: 765,70 867.5,70 970,70 1100,70 1462.25,73 1520,73 1730,80 1095,95 1730,140 775,165 865,165 970,165 1565,173 1477,174 1480,285 1560,285 150,355 1635,575 1635,640 165,650 210,650 1460.12,660 57.3,975.34 60,1035 1182.35,1167.57 1241.94,1264.95 35,1375 659,1404 767,1427 970,1427 875,1428 614,1433 1285,1480 1380,1480 1495,1480 1730,1480 35,1485 1075,1489 143,1490 678,1497 606,1498 770,1498 973,1498 873,1499 921,1506 629.7,1598.11
  other v3: 500.23,72.73 574.48,72.72 590.85,478.2 1223.05,527.77 239.93,578.18 704.43,621.59 833.63,683.94 768.47,684.5 445.71,923.68 1531.33,954.53 1597.76,958.38 464.86,967.62 863.55,1001.58 1313.59,1033.06 1368.58,1033.45 1256.66,1033.84 1421.24,1034.63 1530.67,1035.55 284,1062 195,1139 1235.29,1180.47 1227.19,1218.9 1711.69,1229.78 1713.32,1260.65 1186.59,1411.54 88.6,1424 29.3,1434.1
L_USB_CN_DM: PYLK.A7 PYLK.B7 U6.4 | length 509.5
  Top Layer w6: U6.4@568.15,272.6 569.18,271.57 569.18,254.46 596.04,227.6 816.36,227.6 845.67,256.9 845.67,355.67 855,365 875,365 885.04,354.96 PYLK.A7@885.04,309.89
